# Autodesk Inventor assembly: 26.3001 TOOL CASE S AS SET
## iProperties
Created: 2009-09
Part Number: 26.3001 TOOL CASE S AS SET
Document SubType Name: Assembly
Designer: Administrator
Author: Administrator
